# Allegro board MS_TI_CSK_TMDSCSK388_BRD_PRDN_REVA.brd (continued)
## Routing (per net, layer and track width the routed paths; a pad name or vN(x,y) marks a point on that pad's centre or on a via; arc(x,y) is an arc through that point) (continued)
N14434808: length 4.5
  TOP w0.102: v1(52.6,15.29) 52.55,15.34 52.08,15.34 52.08,15.34 U7.J19
  BOTTOM w0.102: v1(52.6,15.29) 53.03,15.29 53.11,15.22 55.19,15.22 55.66,14.75 C155.1
N14434812: length 4.2
  TOP w0.102: U7.W23 46.48,12.85 v1(46.45,12.83)
  BOTTOM w0.102: C180.1 45.88,10.07 45.87,10.07 45.87,11.54 45.89,11.55 45.89,12.26 v1(46.45,12.83)
N14445231: length 9.8
  TOP w0.102: U1.N1 38.29,47.68 v2(38.31,47.68)
  TOP w0.14: TP9.1 v1(45.5,47.37)
  L06_SIG2 w0.102: 39.55,47.68 v2(38.31,47.68)
  L06_SIG2 w0.119: 39.55,47.68 41.46,47.68 42.1,48.32 42.56,48.32 42.8,48.08 44.78,48.08 v1(45.5,47.37)
N14486422: length 1.7
  TOP w0.14: LD1.2 v1(47.14,50.22)
  BOTTOM w0.14: R88.2 47.1,50.18 v1(47.14,50.22)
N14519770: length 10.5
  TOP w0.102: U7.B6 55.27,21.54 55.71,21.54 56.06,21.9 56.77,21.9 57.31,22.43
  TOP w0.14: 57.31,22.43 57.61,22.74 57.61,24.91 57.96,25.26 57.96,26.32 57.55,26.73 57.55,27.77 58.44,28.67 R63.1
N14522090: length 2.3
  TOP w0.102: U7.AL6 39.51,21.84 38.94,22.4
  TOP w0.14: R73.2 38.62,22.4 38.94,22.4
N14522146: length 8
  TOP w0.102: v1(43.33,19.69) 43.14,19.88 43.14,20.66 42.98,20.82 U7.AF8
  BOTTOM w0.102: 38.94,21.57 39.07,21.44 41.76,21.44 41.79,21.41 42.25,21.41 43.33,20.33 v1(43.33,19.69)
  BOTTOM w0.14: R114.2 38.57,21.94 38.94,21.57
N14553661: length 6.6
  TOP w0.102: v1(45.49,20.85) 45.46,20.85 44.98,20.38 U7.AB9
  BOTTOM w0.102: R116.2 50.47,20.97 50.01,20.51 49.61,20.51 49.12,21 48.56,21 47.98,20.42 46.72,20.42 46.28,20.85 v1(45.49,20.85)
N14554807: length 6.3
  TOP w0.102: TP12.1 38.36,46.1 38,46.1 37,47.1 37,47.27 36.92,47.35 36.92,48.4 U1.L2
N14554839: length 11.7
  TOP w0.102: U1.G3 v1(34.55,49.38)
  TOP w0.14: v1(42.7,47.12) 42.7,47.26 43.06,47.63 TP10.1
  L06_SIG2 w0.102: 39.55,47.36 38.57,47.36 38.48,47.28 38.07,47.28 37.29,48.06 34.88,48.06 34.55,48.38 v1(34.55,49.38)
  L06_SIG2 w0.119: 39.55,47.36 42.05,47.36 42.12,47.3 42.12,47.3 42.3,47.12 v1(42.7,47.12)
N14559309: length 7.3
  TOP w0.102: U7.AJ4 41.48,23.34 41.44,23.38 v1(41.44,23.38)
  BOTTOM w0.102: 40.95,26.59 40.97,26.57 40.97,26.41 41.41,25.98 41.41,25.68 41.99,25.1 41.99,23.93 v1(41.44,23.38)
  BOTTOM w0.14: R104.1 39.51,28.74 39.98,28.27 40.11,28.27 40.57,27.81 40.57,26.98 40.95,26.59
N14559352: length 3
  TOP w0.102: v1(39.32,22.64) 40.66,22.64 40.95,22.34 U7.AK5
  BOTTOM w0.102: v1(39.32,22.64) 39.32,22.76 38.94,23.14
  BOTTOM w0.14: R110.1 38.77,23.31 38.94,23.14
N14559366: length 1.8
  TOP w0.102: v1(39.73,22.23) 39.84,22.34 U7.AL5
  BOTTOM w0.102: R111.1 39.76,22.19 v1(39.73,22.23)
N14559434: length 4.1
  TOP w0.102: U7.AK2 41.27,24.14 41.27,24.52 41.02,24.77 v1(41.02,24.84)
  BOTTOM w0.102: 38.94,24.51 39.51,24.51 39.66,24.36 40.54,24.36 v1(41.02,24.84)
  BOTTOM w0.14: 38.94,24.51 38.57,24.88 R109.1
N14564270: length 1.4
  TOP w0.14: U5.4 64.62,34.44 R52.2
N14564274: length 1.5
  TOP w0.14: R41.2 64.5,34.94 U5.5
N14564278: length 1.7
  TOP w0.14: R38.2 63.99,35.44 U5.6
N14564302: length 1.6
  TOP w0.14: R57.2 64.1,33.94 U5.3
N14564360: length 3.3
  TOP w0.14: R62.2 64.82,31.4 R58.1 64.19,32.21 63.49,32.91 U5.2
N14565290: length 1.5
  BOTTOM w0.14: R92.1 45.19,54.99 45.24,55.04 U12.3
N14565662: length 1.7
  BOTTOM w0.14: U12.2 45.74,54.91 R91.2
N14567220: length 5.7
  TOP w0.102: U7.AB30 45.02,9.84 45.27,9.58 45.27,8.48 45.23,8.44 45.23,7 45.62,6.6 45.62,5.59 45.5,5.46 45.5,5.45 v1(45.44,5.39)
  BOTTOM w0.14: R136.1 45.11,5.07 v1(45.44,5.39)
N14567296: length 5.4
  TOP w0.102: U7.W30 46.76,9.56 46.76,8.86 47.15,8.48 v1(47.15,7.62)
  BOTTOM w0.14: R135.2 48.63,5.82 48.13,6.33 48.13,7.36 47.87,7.62 v1(47.15,7.62)
N14568444: length 2.6
  TOP w0.102: v1(44.43,10.97) 44.29,10.84 U7.AD28
  BOTTOM w0.102: R127.1 43.46,9.79 43.97,10.29 43.97,10.52 v1(44.43,10.97)
N14568464: length 5.4
  TOP w0.102: v1(44.92,12.95) 44.54,13.34 U7.AC23
  BOTTOM w0.102: v1(44.92,12.95) 43.7,11.73 43.7,10.47 42.49,9.25 R128.2
N14568476: length 9.6
  TOP w0.102: U7.AF27 42.58,11.34 v1(42.51,11.42)
  BOTTOM w0.102: 41.86,7.79 41.86,9.48 42.29,9.91 42.55,9.91 43.19,10.55 43.19,11.16 42.94,11.42 v1(42.51,11.42)
  BOTTOM w0.14: 41.86,7.79 41.86,7.06 41.45,6.66 41.45,6.08 40.54,5.17 40.54,4.77 40.07,4.3 R139.1
N14572177: length 2.6
  TOP w0.14: MOD1.42 TP6.1
N14572181: length 5.1
  TOP w0.14: MOD1.43 50.84,54.49 50.76,54.41 49.2,54.41 TP5.1
N14575481: length 4.2
  TOP w0.61: 19.3,66.86 19.36,66.8
  TOP w0.635: 19.36,66.8 L3.1 C2.2 ; A1.1 19.3,66.86
N14575485: length 4.3
  TOP w0.61: 75.89,66.94 75.84,66.94 ; 76.79,64.85 76.78,64.86
  TOP w0.635: 76.78,64.86 76.78,66.05 arc(76.52,66.68) 75.89,66.94 ; 75.84,66.94 L2.1 C1.2 ; A2.1 76.79,64.85
N14575533: length 29.9
  TOP w0.635: R4.2 32.38,63.49 arc(30.8,63.81) 29.46,64.7 28.41,65.75 arc(27.25,66.53) 25.88,66.8 R1.2 C2.1
N14575591: length 9
  TOP w0.635: R5.2 66.19,63.49 arc(67.72,63.8) 69.02,64.66 70.3,65.94 arc(71.4,66.68) L1.1 C1.1
N14595953: length 2.9
  TOP w0.14: R71.2 62.49,25.04 R69.2 63.28,24.49 63.08,24.29 D1.3
N14599932: length 3.4
  TOP w0.102: U7.B19 57.16,15.34 57.31,15.19 57.31,14.99
  TOP w0.14: R78.1 57.46,14.83 57.31,14.99
N14599936: length 2.5
  TOP w0.102: 57.31,15.84 57.24,15.77 55.54,15.77 U7.A18
  TOP w0.14: R77.1 57.6,16.13 57.31,15.84
N14600104: length 1.5
  TOP w0.102: v1(49,10.36) 49.02,10.34 U7.N29
  BOTTOM w0.102: v1(49,10.36) 49.05,10.3 R124.1
N14600252: length 4.9
  TOP w0.102: U7.K31 50.83,9.19 50.83,7.98 50.91,7.91 50.91,4.99 C64.1
N14600256: length 4.9
  TOP w0.102: U7.L31 50.63,9.19 50.63,5.06 50.25,4.68 C63.1
N14600268: length 5.8
  TOP w0.102: U7.H31 52.14,9.34 52.2,9.28 52.2,9.18 52.07,9.04 51.96,9.04 51.88,8.97 51.88,8.74 52.55,8.07 52.55,7.98 52.62,7.91 52.62,7.79 52.76,7.65 52.76,6.91 52.89,6.79 52.89,5.26 52.99,5.16 53.24,5.16 53.37,5.03 C66.1
N14600316: length 5.8
  TOP w0.102: U7.H30 51.68,9.54 51.68,8.65 52.35,7.99 52.35,7.67 52.48,7.53 52.48,6.8 52.61,6.67 52.61,4.94 C65.1
N14600424: length 4.4
  TOP w0.102: R74.2 58.79,21.08 57.72,20 56.47,20 56.47,20 55.82,20 55.68,19.86 55.38,19.86 55.36,19.84 U7.B10
N14600444: length 4.3
  TOP w0.102: U7.B11 55.27,19.64 55.74,19.64 55.87,19.76 56.95,19.76 56.98,19.8 58.52,19.8 58.61,19.89 R76.2
N14634458: length 2.4
  TOP w0.14: SW1.1 37.49,34.02 38.43,33.08 R59.2
N14645029: length 13.4
  TOP w0.14: TP2.1 v1(42.19,60.48) ; U1.L6 36.45,51.47 35.88,51.47 35.88,51.47 v2(35.81,51.47)
  L06_SIG2 w0.102: v2(35.81,51.47) 36.13,51.79 36.13,51.79 38.74,54.4
  L06_SIG2 w0.119: v1(42.19,60.48) 39.09,57.38 39.09,54.76 38.74,54.4
N14648093: length 8
  TOP w0.102: U7.F30 52.98,9.01 53.6,8.39 53.69,8.39 54.28,7.79
  TOP w0.127: 54.53,7.09 C59.2
  TOP w0.14: Y2.1 57.98,6.59 57.27,7.3 56.07,7.3 55.86,7.09 C59.2 ; 54.28,7.79 54.28,7.34 54.53,7.09
N14719275: length 8.9
  TOP w0.102: U1.F4 32.78,49.46 v2(32.78,49.35)
  TOP w0.14: v1(29.49,43.69) 29.49,43.29 R19.1
  BOTTOM w0.102: v2(32.78,49.35) 32.78,46.98 32.11,46.3
  BOTTOM w0.14: 32.11,46.3 v1(29.49,43.69)
N14719324: length 3.2
  TOP w0.102: v1(39.48,24.97) 39.78,25.27 40.12,25.27 40.46,24.93 40.46,24.85 U7.AK1
  BOTTOM w0.102: v1(39.48,24.97) 39.17,25.27 39.17,25.68 39,25.85
  BOTTOM w0.14: 39,25.85 R106.1
N14776629: length 7
  TOP w0.102: v1(44.44,10.36) 44.42,10.34 U7.AD29
  BOTTOM w0.102: v1(44.44,10.36) 43.97,9.89 43.97,7.79
  BOTTOM w0.14: R138.2 42.61,4.68 43.97,6.04 43.97,7.79
N14776712: length 5.4
  TOP w0.102: U7.AD30 43.98,9.02 44.15,8.85 44.15,6.08 44.12,6.05 v1(44.12,5.61)
  BOTTOM w0.14: v1(44.12,5.61) 44.12,5.56 43.84,5.29 R137.1
N14776785: length 4.8
  TOP w0.102: U7.N24 49.01,12.84 v1(48.99,12.81)
  BOTTOM w0.102: R129.1 50.49,9.2 49.38,10.31 49.38,10.51 49.38,10.52 49.38,11.1 49.37,11.11 49.37,12.39 49.37,12.4 49.37,12.44 v1(48.99,12.81)
N14776789: length 3.1
  TOP w0.102: v1(50.48,10.33) 50.47,10.34 U7.M29
  BOTTOM w0.102: v1(50.48,10.33) 50.78,10.02 50.79,10.02 50.83,9.98 52.12,9.98 52.65,9.46 R123.1
N14783196: length 10.5
  TOP w0.102: U7.W31 46.48,8.86 46.57,8.77 46.57,8.76 46.77,8.57 46.77,7.78 46.77,7.78 46.77,7.46 46.77,7.46 46.77,7.4 46.97,7.2 v1(47.73,7.2)
  L03_SIG1 w0.119: v1(47.73,7.2) 47.28,6.75 47.28,6.31 48.72,4.88 51.17,4.88 51.75,5.46 v1(52.1,5.46)
  BOTTOM w0.14: v1(52.1,5.46) 52.24,5.6 RA13.4
N14783200: length 11.7
  TOP w0.102: v1(47.7,6.48) 47.39,6.18 46.23,6.18 45.9,6.51 45.9,6.71 45.52,7.09 45.52,7.79 45.48,7.83 45.48,8.4 U7.AA30
  L03_SIG1 w0.119: v1(51.34,5.63) 50.85,5.15 49.04,5.15 v1(47.7,6.48)
  BOTTOM w0.14: v1(51.34,5.63) 51.64,5.33 51.64,5.32 51.98,4.98 52.28,4.98 52.4,5.1 RA13.3
N14783204: length 9.7
  TOP w0.102: U7.U29 47.04,10.34 v1(47.02,10.36)
  L06_SIG2 w0.102: 48.2,7.79 47.93,8.06 47.93,8.06 47.02,8.97 v1(47.02,10.36)
  L06_SIG2 w0.119: v1(50.15,6.74) 49.25,6.74 48.2,7.79
  BOTTOM w0.14: RA13.2 51.71,4.6 50.83,5.49 50.83,6.05 v1(50.15,6.74)
N14783208: length 12.3
  TOP w0.102: v1(46.47,11.63) 46.18,11.34 U7.Y27
  L06_SIG2 w0.102: 47.82,7.79 45.88,9.73 45.88,11.03 v1(46.47,11.63)
  L06_SIG2 w0.119: 47.82,7.79 49.5,6.1 v1(50.14,6.1)
  BOTTOM w0.14: RA13.1 51.5,4.1 50.14,5.46 v1(50.14,6.1)
N15013442: length 2.3
  TOP w0.635: R2.2 J1.1
N15014410: length 2.3
  TOP w0.635: J2.1 R3.2
N15102842: length 10.1
  TOP w0.102: v1(57.06,11.6) 57.02,11.56 57.31,11.56 ; U7.M21 v1(49.58,14.34)
  TOP w0.14: R79.2 57.31,11.56
  BOTTOM w0.102: v1(57.06,11.6) 56.21,12.45 54.77,12.45 54.16,13.06 52.14,13.06 51.92,12.83 51.06,12.83 50.89,13 50.89,13.03 50.89,13.04 50.89,13.54 50.56,13.87 50.06,13.87 v1(49.58,14.34)
N15102865: length 4
  TOP w0.102: U7.E30 53.18,9.54 53.18,9.24 53.78,8.64 53.84,8.64 v1(54.68,7.79)
  BOTTOM w0.14: v1(54.68,7.79) 55.49,6.99 R134.2
N15102869: length 5.4
  TOP w0.102: v1(53.97,11.12) 53.69,10.84 U7.E28 ; 57.31,9.65 57.18,9.78 v1(56.87,9.78)
  TOP w0.14: 57.31,9.65 R80.2
  BOTTOM w0.102: v1(56.87,9.78) 56.87,10.67 56.42,11.12 v1(53.97,11.12)
N15102988: length 4.6
  TOP w0.102: U7.AG2 42.48,23.86 42.76,24.14 42.76,25.8 42.27,26.29 42.27,26.59
  TOP w0.14: R65.2 41.39,26.98 41.88,26.98 42.27,26.59
N15110091: length 1.5
  TOP w0.14: R54.1 59.39,34.44 U5.13
N15110100: length 1.3
  TOP w0.14: U5.12 58.88,34.94 R47.1
N15110106: length 1.4
  TOP w0.14: U5.11 59.26,35.44 R39.1
N15110404: length 7.1
  BOTTOM w0.14: U12.11 43.74,60.5 44.42,61.18 46.72,61.18 47.17,60.73 47.17,59.87 47.3,59.74 R87.1
N15110444: length 1.8
  BOTTOM w0.14: U12.6 43.74,55.16 43.04,54.47 R90.2
N15123588: length 2.3
  TOP w0.102: U7.Y29 46.43,10.34 v1(46.46,10.36)
  BOTTOM w0.102: v1(46.46,10.36) 46.91,9.91 47.34,9.91 47.87,9.38 R125.2
N15123674: length 1.8
  TOP w0.102: v1(45,10.36) 45.02,10.34 U7.AA29
  BOTTOM w0.102: v1(45,10.36) 44.48,9.84 R126.1
N15123798: length 6.7
  TOP w0.102: v1(44.98,10.96) 45.1,10.84 U7.AA28
  BOTTOM w0.102: v1(44.98,10.96) 45.38,10.56 45.38,10.17 45.08,9.87 45.08,7.79
  BOTTOM w0.14: RA12.5 45.08,6.67 45.08,7.79
N15123807: length 7.6
  TOP w0.102: U7.AA26 45.19,11.84 v1(44.99,11.63)
  BOTTOM w0.102: v1(44.99,11.63) 45.58,11.04 45.58,10.09 45.37,9.88 45.37,7.79
  BOTTOM w0.14: 45.37,7.79 45.37,7.04 46.26,6.16 46.41,6.16 46.69,5.88 RA12.6
N15123817: length 4.5
  TOP w0.102: U7.Y31 45.98,8.96 46.51,8.42 46.51,7.14 46.39,7.02 v1(46.39,6.59)
  BOTTOM w0.14: v1(46.39,6.59) 46.71,6.27 46.89,6.27 47.19,5.97 RA12.7
N15123828: length 5.7
  TOP w0.102: U7.Y30 45.98,9.84 45.68,9.54 45.68,8.87 46.26,8.3 46.26,7.81 46.15,7.71 46.15,7.32
  TOP w0.14: 46.15,7.32 v1(46.03,7.2)
  BOTTOM w0.14: v1(46.03,7.2) 46.48,7.2 47.27,6.41 47.27,6.31 47.69,5.89 RA12.8
N15124532: length 6.1
  TOP w0.102: U7.AG6 42.48,22.23 42.43,22.27 v1(42.43,22.33)
  BOTTOM w0.102: v1(42.43,22.33) 42.43,22.76 42.4,22.79 42.4,26.57 42.38,26.59
  BOTTOM w0.14: 42.38,26.59 42.29,26.68 R105.1
N15124704: length 1.7
  TOP w0.14: MOD1.6 v1(65.89,53.79)
  BOTTOM w0.14: R93.2 65.88,53.79 v1(65.89,53.79)
N15124708: length 1.7
  TOP w0.14: MOD1.8 v1(65.89,55.19)
  BOTTOM w0.14: v1(65.89,55.19) 65.85,55.16 R89.2
N15124784: length 1.8
  TOP w0.14: MOD1.10 v1(65.89,56.59)
  BOTTOM w0.14: RA5.4 65.66,56.82 v1(65.89,56.59)
N15124788: length 3
  TOP w0.14: MOD1.11 v1(66.55,57.29)
  BOTTOM w0.14: v1(66.55,57.29) 66.1,57.29 66.07,57.32 RA5.3
N15124799: length 3.2
  TOP w0.14: MOD1.13 v1(66.55,58.69)
  BOTTOM w0.14: v1(66.55,58.69) 65.98,58.69 65.61,58.32 RA5.1
N15124807: length 1.8
  TOP w0.14: MOD1.12 v1(65.89,57.99)
  BOTTOM w0.14: v1(65.89,57.99) 65.72,57.82 RA5.2
N15124875: length 2.7
  TOP w0.14: MOD1.60 61.15,49 61.14,48.99 61.14,47.85 61.61,47.38 R13.2
N15140205: length 8.4
  TOP w0.14: U6.L8 25.91,16.95 25.91,15.73 25.16,14.97 R119.2
N15266407: length 1.9
  TOP w0.102: U7.AC8 44.85,20.84 44.92,20.91 v1(44.93,20.91)
  BOTTOM w0.102: v1(44.93,20.91) 44.6,20.91 44.28,21.23 R115.1
N15454827: length 1.7
  TOP w0.102: v1(47.01,12.41) 47.01,12.41 47.48,11.94 U7.U26
  BOTTOM w0.102: R133.1 47.14,12.41 v1(47.01,12.41)

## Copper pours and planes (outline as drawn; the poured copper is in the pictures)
DGND on TOP: 68.66,46.07 68.66,59.64 68.41,59.89 64.57,59.89 63.81,60.66 54.06,60.66 53.32,59.92 52,59.92 50.36,61.56 7.78,61.56 7.78,68.81 8.74,68.81 8.74,69.49 11.36,69.49 11.36,69.33 14.63,69.33 14.63,69.27 20.96,69.27 20.96,69.49 78.03,69.49 78.77,68.76 78.77,46.07 ; 2 cut-outs
DGND on TOP: 20.6,50.67 22.13,50.67 22.64,51.18 22.89,51.18 23.02,51.05 23.02,50.29 22.89,50.17 20.73,50.17 20.6,50.29
DGND on TOP: 37.11,52.45 38.38,52.45 38.76,52.83 38.76,53.21 38.64,53.34 37.88,53.34 37.37,52.83 37.24,52.83 37.11,52.71
DGND on TOP: 8.39,0.76 7.78,1.37 7.78,60.96 12.98,60.96 13.11,61.09 35.46,61.09 35.59,60.96 50.14,60.96 51.52,59.59 53.8,59.59 54.11,59.89 63.91,59.89 64.65,59.16 67.59,59.16 67.59,45.47 79.02,45.47 79.02,1.7 78.08,0.76 ; 22 cut-outs
DGND on TOP: 35.08,53.98 35.08,51.94 35.21,51.82 35.34,51.82 35.46,51.94 35.46,53.09 36.35,53.98 36.35,54.99 36.22,55.12 35.84,55.12 35.84,54.74
DGND on TOP: 13.87,22.73 14.63,21.97 14.63,20.19 15.78,20.19 15.9,20.32 15.9,24.77 15.65,25.02 14,25.02 13.87,24.89
DGND on TOP: 41.81,56.13 42.07,56.39 42.07,58.17 41.81,58.42 38.89,58.42 38.76,58.29 38.76,56.26 38.89,56.13
DGND on TOP: 23.78,48.01 23.78,47.12 23.91,46.99 25.56,46.99 25.68,47.12 25.68,48.01 25.56,48.13 23.91,48.13
DGND on TOP: 35.21,50.17 35.72,50.17 35.97,49.91 35.97,49.53 36.1,49.4 36.1,49.28 35.97,49.15 35.72,49.15 35.59,49.02 35.59,46.99 36.1,46.48 37.11,46.48 37.75,45.85 38.13,45.85 39.15,44.83 39.15,43.18 39.02,43.05 38.26,43.05 38.13,43.18 38.13,44.58 37.62,45.09 36.73,45.09 35.08,46.74 35.08,50.04
DGND on BOTTOM: 43.88,32.07 43.88,30.82 44.02,30.68 49.7,30.68 50.11,30.26 50.11,28.26 50.51,27.86 51.77,27.86 52.09,28.18 52.09,31.57 51.89,31.77 49.25,31.77 48.85,32.16 48.85,33.21 48.55,33.51 47.04,33.51 46.63,33.1 46.63,32.61 46.18,32.16 44.04,32.16 44.01,32.19
DGND on BOTTOM: 8.47,0.64 7.51,1.6 7.51,68.33 7.99,68.81 8.79,68.81 8.87,68.73 10.01,68.73 10.54,69.27 10.54,69.22 20.96,69.22 20.96,69.49 78.01,69.49 79.04,68.46 79.04,1.8 77.88,0.64 49.2,0.64 48.24,1.6 41.94,1.6 40.97,0.64 ; 32 cut-outs
DGND on L02_GND1: 79.04,45.72 79.04,1.86 77.82,0.64 49.2,0.64 48.24,1.6 41.94,1.6 40.97,0.64 8.47,0.64 7.51,1.6 7.51,61.47 50.22,61.47 51.9,59.79 53.37,59.79 53.9,60.33 63.88,60.33 64.49,59.72 67.03,59.72 67.59,59.16 67.59,45.85 67.72,45.72 ; 4 cut-outs
DGND on L04_PWR1, L05_PWR2: 68.66,46.48 68.66,59.64 68.41,59.89 64.57,59.89 64.01,60.45 53.85,60.45 53.32,59.92 52,59.92 50.32,61.6 38.13,61.6 37.11,60.58 7.42,60.58 7.42,68.23 8,68.81 9.15,68.81 9.67,69.33 20.95,69.33 20.95,69.49 77.83,69.49 79.12,68.2 79.12,46.48
DGND on L07_GND2: 8.47,0.64 7.51,1.6 7.51,68.33 7.99,68.81 8.79,68.81 8.87,68.73 10.01,68.73 10.61,69.33 20.95,69.33 20.95,69.49 78.01,69.49 79.04,68.46 79.04,1.8 77.88,0.64 49.2,0.64 48.24,1.6 41.94,1.6 40.97,0.64 ; 5 cut-outs
VCC_3V3 on TOP: 11.84,21.21 11.84,18.8 11.97,18.67 15.02,18.67 15.14,18.8 15.14,19.81 15.02,19.94 14.51,19.94 14.51,20.7 14.13,21.08 14.13,22.23 12.98,22.23 12.98,21.34 12.86,21.21
VCC_3V3 on BOTTOM: 35.34,40.77 35.34,36.45 35.59,36.2 36.48,36.2 36.48,40.64 36.22,40.89 35.46,40.89
VCC_3V3 on L04_PWR1: 49.89,60.55 51.57,58.88 53.98,58.88 54.51,59.41 63.3,59.41 63.94,58.78 65.92,58.78 67.34,57.35 67.34,45.54 67.42,45.47 78.9,45.47 78.92,45.44 78.92,1.45 78.16,0.69 49.25,0.69 48.29,1.65 45.19,1.65 44.23,0.69 8.36,0.69 7.8,1.25 7.8,59.49 37.57,59.49 38.64,60.55 ; 9 cut-outs
VCC_3V3 on L05_PWR2: 7.8,22.61 13.49,22.61 14,23.11 14,27.43 17.3,30.73 21.21,30.73 25.05,34.57 25.05,35.43 25.18,35.56 33.3,35.56 35.72,37.97 39.4,37.97 45.11,43.69 45.11,46.1 55.86,46.1 56.54,45.42 56.54,26.92 49.56,19.94 49.05,19.94 48.54,20.45 46.64,20.45 46.38,20.7 39.78,20.7 37.75,22.73 37.75,29.72 36.99,30.48 28.03,30.48 27.13,29.58 27.13,28.04 27.63,27.55 28.36,27.55 28.59,27.31 28.59,25.94 28.31,25.65 22,25.65 20.35,24 20.35,4.06 21.62,2.79 38.76,2.79 45.62,9.65 45.62,11.94 45.75,12.07 45.75,13.34 45.24,13.84 45.24,15.88 45.62,16.26 45.62,20.07 45.75,20.19 46.89,20.19 47.02,20.07 47.02,13.34 48.67,11.68 62.39,11.68 69.12,18.42 69.12,43.05 67.99,44.18 67.99,45.56 68.1,45.67 78.92,45.67 78.92,1.68 77.93,0.69 49.18,0.69 48.24,1.63 45.19,1.63 44.25,0.69 8.36,0.69 7.8,1.25 ; 7 cut-outs
VCC_5V0 on TOP: 11.76,60.05 10.75,60.05 10.74,60.03 8.63,60.03 8.41,59.82 8.41,48.9 8.69,48.62 10.65,48.62 10.7,48.57 15.07,48.57 15.12,48.62 15.12,49.91 11.89,49.91 11.76,50.04
VCC_5V0 on TOP: 39.78,50.04 39.78,49.91 39.53,49.66 37.75,49.66 37.75,49.15 38,49.15 38.13,49.28 39.53,49.28 39.78,49.02 39.78,48.64 39.91,48.51 41.3,48.51 41.43,48.64 41.43,49.91 41.05,50.29 40.03,50.29
VCC_5V0 on TOP: 23.14,34.67 24.01,34.67 24.29,34.95 24.29,38 24.54,38.25 24.54,40.77 22,40.77 21.75,41.02 21.75,41.4 21.49,41.66 18.19,41.66 18.06,41.53 18.06,39.24 22.64,39.24 23.14,38.74
VCC_5V0 on TOP: 30.38,50.55 31.02,51.18 31.02,51.44 30.89,51.56 30.64,51.56 30.26,51.18 29.24,51.18 28.35,52.07 23.78,52.07 23.65,51.94 23.65,50.67 23.78,50.55
VCC_5V0 on BOTTOM: 16.29,41.15 16.29,39.24 16.41,39.12 22.25,39.12 22.28,39.14 23.12,39.14 23.22,39.24 23.22,39.8 21.49,41.53 16.67,41.53
VCC_5V0 on L05_PWR2: 46.83,53.66 46.83,48.07 44.86,46.1 44.86,43.94 39.15,38.23 35.72,38.23 33.18,35.69 24.86,35.69 24.86,34.91 20.87,30.93 17.11,30.93 13.62,27.43 13.62,26.29 12.98,25.65 12.98,23.11 12.67,22.8 8.54,22.8 7.8,23.54 7.8,59.82 8,60.02 36.66,60.02 37.25,59.42 37.25,57.04 37.82,56.47 44.02,56.47 ; 4 cut-outs
VDD_DDR on TOP: 33.43,28.83 33.81,28.45 38,28.45 38.38,28.83 38.38,30.61 37.11,30.61 36.61,31.12 36.61,33.4 35.46,34.54 35.46,38.99 35.21,39.24 33.15,39.24 33.1,39.19 33.1,34.06 33.43,33.73
VDD_DDR on L04_PWR1: 19.92,5.02 16.6,8.33 16.6,12.24 17.1,11.75 19.79,11.75 20.03,11.99 20.03,16.43 20.1,16.5 20.1,23.5 22.06,25.46 22.06,28.77 25.19,28.77 25.43,29.01 25.43,32 25.87,32.45 34.11,32.45 41.11,25.45 41.11,22.11 40.16,21.15 40.16,14.48 40.03,14.35 40.03,8.4 36.65,5.02
VDD_DDR on L05_PWR2: 39.53,20.45 45.18,20.45 45.43,20.19 45.43,16.64 44.86,16.07 44.86,13.78 45.43,13.21 45.43,9.78 38.7,3.05 21.75,3.05 20.67,4.13 20.67,23.75 22.19,25.27 28.57,25.27 28.97,25.67 28.97,27.6 28.64,27.94 27.73,27.94 27.46,28.2 27.46,29.44 28.25,30.23 36.86,30.23 37.49,29.59 37.49,22.48 ; 1 cut-out
VDDR_VTT on TOP: 17.07,14.96 19.18,14.96 19.43,15.22 19.43,20.07 19.18,20.32 17.07,20.32 16.82,20.07 16.82,15.22
VDDR_VTT on BOTTOM: 23.91,30.61 24.62,30.61 24.79,30.43 24.79,30.02 25.1,29.72 25.35,29.72 25.63,30 25.89,30 25.96,29.92 25.96,29.08 25.76,28.88 24.08,28.88 23.7,29.26 23.7,30.4
VDDR_VTT on BOTTOM: 18.27,16 17.68,15.42 17.68,12.45 17.81,12.32 18.27,12.32 18.29,12.29 18.88,12.29 18.93,12.35 18.93,15.77 18.9,15.8 18.9,16.08 19.16,16.33 19.16,17.98 19.71,18.54 22.38,18.54 22.51,18.42 23.78,18.42 23.91,18.29 23.91,17.4 24.54,17.4 24.67,17.53 24.67,18.92 24.92,19.18 24.92,21.21 23.78,21.21 23.27,20.7 22.18,20.7 22.18,21.41 22,21.59 21.21,21.59 20.88,21.92 20.88,24.67 21.14,24.92 23.52,24.92 23.55,24.89 27.08,24.89 27.08,25.91 26.83,26.16 26.83,27.2 26.78,27.26 25.02,27.26 25.02,26.09 24.92,25.99 23,25.99 22.93,26.06 22.93,27.13 22.24,27.13 21.68,27.69 21.24,27.69 21.11,27.56 21.11,25.78 19.69,25.78 19.56,25.65 19.56,22.73 19.33,22.51 19.33,19.43 19.21,19.3 18.27,19.3
VDDR_VTT on L04_PWR1: 17.25,12.13 16.6,12.78 16.6,33.53 17.68,33.53 18.76,32.45 19.75,32.45 19.76,32.45 24.49,32.45 24.9,32.04 24.9,29.46 24.58,29.15 21.68,29.15 21.68,25.7 19.65,23.67 19.65,12.14 19.64,12.13
(no net) on TOP: 31.96,41.02 31.96,45.21 32.51,45.76 32.51,48.13 33.18,48.8 33.18,49.4 33.3,49.53 33.43,49.53 33.56,49.4 33.56,48.77 32.92,48.13 32.92,46.29 32.98,46.23 33.68,46.23 33.81,46.36 33.81,48.85 34.19,48.85 34.19,45.97 34.7,45.47 34.7,44.58 35.21,44.07 35.21,42.8 33.3,42.8 33.3,41.02
(no net) on L03_SIG1: 8.47,0.64 7.51,1.6 7.51,61.47 50.22,61.47 51.9,59.79 53.37,59.79 53.9,60.33 63.88,60.33 64.49,59.72 67.14,59.72 67.59,59.26 67.59,45.85 67.72,45.72 79.04,45.72 79.04,1.86 77.82,0.64 49.2,0.64 48.24,1.6 41.94,1.6 40.97,0.64 ; 106 cut-outs
(no net) on L06_SIG2: 79.04,45.72 79.04,1.86 77.82,0.64 49.2,0.64 48.24,1.6 41.94,1.6 40.97,0.64 8.47,0.64 7.51,1.6 7.51,61.47 50.22,61.47 51.9,59.79 53.37,59.79 53.9,60.33 63.88,60.33 64.49,59.72 67.03,59.72 67.59,59.16 67.59,45.85 67.72,45.72 ; 78 cut-outs
BB_PMIC_3V3 on TOP: 9.94,42.55 9.94,40.64 11.21,39.37 13.24,39.37 13.49,39.62 13.49,41.78 12.73,42.55
BB_PMIC_3V3 on BOTTOM: 12.48,38.1 12.6,38.23 12.6,42.16 12.48,42.29 10.32,42.29 10.25,42.23 8.73,42.23 8.16,41.66 8.16,36.7 8.28,36.58 10.7,36.58 10.82,36.7 11.71,36.7 11.71,36.96 10.82,36.96 10.57,37.21 9.94,37.21 9.81,37.34 9.81,37.85 10.06,38.1
BB_VCC3V3 on TOP: 11.33,20.57 11.46,20.7 11.46,21.34 11.59,21.46 12.6,21.46 12.73,21.59 12.73,22.23 12.6,22.35 8.28,22.35 8.16,22.23 8.16,20.7 8.28,20.57
BB_VCC3V3 on BOTTOM: 12.73,20.57 12.86,20.7 12.86,21.97 12.73,22.1 10.7,22.1 10.57,21.97 8.41,21.97 8.28,21.84 8.28,20.7 8.41,20.57
CORE_CVDD on TOP: 16.92,44.07 16.92,42.67 17.3,42.29 21.49,42.29 21.75,42.55 21.75,43.94 21.62,44.07
CORE_CVDD on BOTTOM: 44.12,30.28 44.12,29.31 44.25,29.18 45.33,29.18 45.7,29.56 48.09,29.56 48.15,29.62 48.15,30.25 48.05,30.35 44.2,30.35
CORE_CVDD on L04_PWR1: 41.49,21.95 41.49,25.61 34.27,32.83 18.63,32.83 17.11,34.35 17.11,42.85 18.65,44.39 21.87,44.39 22.32,43.94 22.32,39.04 24.33,37.02 36.78,37.02 39.7,34.1 46.81,34.1 47.53,33.39 47.53,31.37 48.8,30.1 48.8,27.69 47.98,26.87 47.98,21.69 47.55,21.25 47.55,15.13 46.26,13.84 45.24,13.84 45.11,13.72 45.11,13.46 44.86,13.21 40.54,13.21 40.42,13.34 40.42,20.87
CORE_CVDD on L05_PWR2: 46.26,19.16 46.96,19.16 47.78,18.34 50.12,18.34 50.73,17.73 50.73,16.13 50.64,16.05 48.63,16.05 47.66,15.08 45.97,15.08 45.48,15.57 45.48,16.14 45.67,16.33 45.67,19.01 45.85,19.18 46.24,19.18
CVDD_ARM on TOP: 24.03,42.67 24.03,41.02 22.13,41.02 22.13,42.67
CVDD_ARM on L04_PWR1: 49.75,19.24 52.23,21.72 52.23,35.05 50.58,36.7 39.02,36.7 35.08,40.64 24.03,40.64 23.52,41.15 23.52,42.55 24.67,43.69 35.07,43.69 39,39.75 39.02,39.75 39.27,39.5 50.6,39.5 51.21,40.11 53.9,40.11 57.18,36.83 57.18,26.29 56.8,25.91 56.8,24.77 54.64,22.61 54.64,19.05 54.39,18.8 52.35,18.8 51.68,18.12 51.68,15.46 50.96,14.73 49.56,14.73 49.46,14.83 49.46,18.31 49.75,18.61
CVDD_HDVICP on TOP: 40.14,41.23 40.14,40.51 40.01,40.39 40.01,40.01 40.16,39.85 41.18,39.85 41.48,40.16 41.48,40.87 41.71,41.1 41.71,41.66 41.3,41.66 40.87,41.23
CVDD_HDVICP on L04_PWR1: 48.16,13.84 48.16,13.72 46.51,12.07 45.37,12.07 45.37,13.64 45.44,13.72 46.26,13.72 47.65,15.11 47.65,21.21 48.16,21.72 48.16,26.67 49.69,28.19 49.69,30.1 48.16,31.62 48.16,33.53 47.53,34.16 38.76,34.16 35.59,37.34 24.29,37.34 22.51,39.12 22.51,44.07 23.52,45.09 36.48,45.09 41.05,40.51 41.05,40.13 40.8,39.88 39.4,39.88 35.21,44.07 24.54,44.07 23.27,42.8 23.27,40.77 23.91,40.13 34.95,40.13 38.76,36.32 50.58,36.32 51.85,35.05 51.85,21.72 49.2,19.08 49.2,14.89
PMIC_3V3 on TOP (solid shape): 33.94,48.85 33.98,48.83 33.99,48.79 34,48.73 34,45.83 34.45,45.38 34.45,44.49 35.08,43.86 35.08,43.08 35.01,43.01 35.01,42.8 33.3,42.8 33.3,42.26 33.15,41.87 33.3,41.48 33.3,41.02 31.96,41.02 31.96,45.21 32.51,45.76 32.51,47.19 32.52,47.26 32.53,47.33 32.53,48.16 32.62,48.24 32.7,48.24 32.75,48.25 32.8,48.25 32.89,48.23 32.92,48.14 32.91,48.07 32.92,47.99 32.92,47.47 32.74,47.3 32.74,46.74 32.79,46.54 32.92,46.39 32.92,46.29 32.98,46.23 33.68,46.23 33.81,46.36 33.81,48.85
PMIC_3V3 on TOP: 40.16,53.59 40.54,53.98 41.3,53.98 41.3,55.63 41.18,55.75 37.88,55.75 37.75,55.63 37.75,54.1 36.35,52.71 36.35,51.94 36.48,51.82 36.86,51.82 36.86,52.71 37.75,53.59
PMIC_3V3 on TOP: 11.84,36.96 16.41,36.96 16.79,37.34 16.79,38.48 16.29,38.99 15.4,38.99 15.14,39.24 13.49,39.24 13.24,38.99 10.57,38.99 10.32,39.24 9.05,39.24 8.79,38.99 8.79,36.7 9.05,36.45 11.33,36.45
PMIC_3V3 on L05_PWR2: 38.67,51.08 38.67,50.32 34.57,46.23 34.57,41.72 34.19,41.34 33.68,41.34 33.3,40.96 28.61,40.96 27.62,41.94 19.49,41.94 16.41,38.86 16.41,37.34 15.78,36.7 12.73,36.7 12.48,36.96 12.48,38.23 13.05,38.8 13.05,42.29 14.89,44.13 14.89,48.77 15.27,49.15 21.87,49.15 22.57,49.85 26.32,49.85 29.82,53.34 32.99,53.34 33.87,54.23 33.87,56 34.35,56.48 42.35,56.48 43.02,55.82 43.02,54.62 42.19,53.79 38.63,53.79 38.07,53.22 38.07,51.69
REFGND on L02_GND1: 31.58,55.6 31.58,58.57 31.8,58.8 33.53,58.8 33.94,59.21 33.94,59.84 33.99,59.89 35.69,59.89 35.92,59.67 35.92,55.78 35.49,55.35 34.47,55.35 34.12,54.99 34.12,53.54 34.32,53.34 34.32,53.09 34.19,52.96 34.19,52.58 34.46,52.31 34.46,52.06 34.24,51.84 33.18,51.84 33.13,51.89 33.13,55.17 32.97,55.32 31.91,55.32 31.88,55.3
TPS_CORE_CVDD on TOP: 16.79,46.61 16.79,44.96 17.05,44.7 21.75,44.7 22.13,45.09 22.13,46.61 22,46.74 16.92,46.74
TPS_CORE_CVDD on TOP: 19.84,50.55 19.97,50.67 19.97,58.67 19.33,59.31 15.65,59.31 15.27,58.93 15.27,50.65 15.37,50.55
TPS_CORE_CVDD on L03_SIG1: 20.03,49.02 21.94,47.11 21.94,44.64 21.87,44.58 16.03,44.58 15.9,44.7 15.9,53.32 15.47,53.75 15.47,59.23 15.75,59.51 19.82,59.51 20.03,59.3
TPS_CVDD_ARM on TOP: 25.43,46.86 25.43,42.42 27.97,42.42 28.1,42.29 28.1,41.15 24.41,41.15 24.41,43.05 22.25,43.05 22.25,44.83 22.38,44.96 22.38,46.23 23.02,46.86
TPS_CVDD_HDVICP on TOP: 37.77,40.01 39.88,40.01 39.88,42.65 39.58,42.95 39.43,42.95 39.15,42.67 39.15,42.55 37.8,42.55 37.44,42.9 35.44,42.9 35.39,42.85 35.39,41.62 35.58,41.42 37.04,41.42 37.07,41.39 37.07,40.46 37.18,40.35 37.77,40.35
TPS_VDAC_1V8 on TOP: 39.65,53.09 39.65,52.32 39.4,52.07 39.02,52.07 38.51,51.56 37.75,51.56 37.75,51.18 39.15,51.18 39.27,51.31 40.42,51.31 40.54,51.44 40.54,53.09 40.42,53.21 39.78,53.21
TPS_VDDA_1V8 on TOP: 34.57,55.12 34.57,52.83 34.45,52.71 34.45,52.58 34.57,52.45 34.83,52.45 34.95,52.58 34.95,54.1 35.59,54.74 35.59,55.25 34.7,55.25
TPS_VDDA_1V8 on TOP: 36.1,60.83 36.1,58.8 36.22,58.67 38.51,58.67 38.64,58.8 41.18,58.8 41.3,58.93 41.3,60.71 41.18,60.83
TPS_VDDA_1V8 on L03_SIG1: 52.68,47.78 59.11,47.78 59.47,47.42 60.43,47.42 60.79,47.78 63.4,47.78 63.66,47.52 63.66,47.17 62.01,45.52 57.18,45.52 54.64,42.98 53.17,42.98 52.4,43.74 52.4,47.5
TPS_VDDA_1V8 on L05_PWR2: 48.67,11.94 48.04,12.57 48.04,14.1 47.82,14.31 47.82,14.95 48.82,15.95 50.17,15.95 50.27,15.85 51.9,15.85 52.28,16.23 52.28,18.24 51.87,18.64 47.27,18.64 47.27,20.19 48.54,20.19 48.92,19.81 49.69,19.81 56.8,26.92 56.8,34.8 57.94,35.94 57.94,46 57.59,46.36 48.29,46.36 47.15,47.5 47.15,54.08 43.97,57.25 38.26,57.25 38.26,60.73 38.61,61.09 50.04,61.09 51.79,59.34 53.65,59.34 54.11,59.79 63.1,59.79 63.99,58.9 65.92,58.9 66.3,59.28 66.86,59.28 67.59,58.55 67.59,44.07 68.86,42.8 68.86,18.54 62.26,11.94 ; 7 cut-outs
TPS_VDDA_1V8 on L06_SIG2: 59.26,32.51 64.62,32.51 65.49,33.38 65.49,36.58 66.91,38 66.91,41.33 66.07,42.16 61.29,42.16 60.96,42.5 60.96,44.35 63.02,46.41 63.63,46.41 64.34,47.12 64.34,56.62 63,57.96 50.85,57.96 50.27,57.38 50.27,47.63 51.03,46.86 53.78,46.86 56.87,49.96 59.39,49.96 60.13,49.23 60.13,48.03 57.94,45.85 57.94,40.67 59.21,39.4 59.21,37.44 59.19,37.42 59.19,32.59
N11847334 on TOP: 32.29,46.1 31.14,44.96 29.87,44.96 28.22,43.31 25.81,43.31 25.81,44.32 26.83,44.32 28.22,45.72 30.64,45.72 31.78,46.86 31.78,48.64 32.03,48.9 32.77,48.9 32.85,48.82 32.85,48.69 32.73,48.58 32.54,48.58 32.29,48.32
N11848351 on TOP: 34.45,48.9 34.83,48.9 34.83,46.74 36.73,44.83 37.58,44.83 37.75,44.66 37.75,44.66 37.83,44.58 37.83,43.54 37.79,43.5 36.76,43.5 36.73,43.47 36.73,43.5 35.59,43.5 35.59,44.07 34.95,44.7 34.95,45.59 34.45,46.1
N11848810 on TOP: 36.35,57.4 36.35,55.5 36.73,55.12 36.73,54.36 36.61,54.23 36.61,53.98 35.72,53.09 35.72,51.94 35.84,51.82 36.05,51.82 36.15,51.92 36.15,52.88 37.49,54.23 37.49,55.63 38.38,56.52 38.38,57.4
N12973023 on TOP: 25.68,48.39 26.06,48.01 26.83,48.01 28.48,49.66 28.99,49.66 29.11,49.78 30.26,49.78 30.26,50.17 27.72,50.17 27.33,49.78 16.16,49.78 15.65,49.28 15.65,48.39 15.52,48.26 13.49,48.26 13.36,48.13 13.36,46.48 13.62,46.23 15.27,46.23 16.03,46.99 22.64,46.99 24.03,48.39
N14067125 on TOP: 24.92,37.72 24.67,37.47 24.67,35.94 24.92,35.69 26.57,35.69 27.21,36.32 29.49,36.32 29.87,35.94 29.87,33.66 31.91,33.66 32.31,34.06 32.31,39.12 27.72,39.12 26.32,37.72
N14067125 on BOTTOM: 25.94,34.67 25.68,34.67 25.56,34.8 25.56,36.07 25.81,36.32 27.46,36.32 27.59,36.2 27.59,35.69 26.7,35.69 26.06,35.05 26.06,34.8

Small or netless copper shapes (teardrops, artwork), in the pictures only: 731 on TOP, 586 on BOTTOM, 316 on L03_SIG1, 3 on L04_PWR1, 11 on L05_PWR2, 323 on L06_SIG2

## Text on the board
Ref Des/Assembly Bottom: D | TMDSCSK388_PRDN_REVA BOTTOM ASSEMBLY.
Ref Des/Silkscreen Bottom: C | B | For evaluation only; not FCC approved for resale | ASSY REV:
User.Comments: CR_UNNAMED_1
Ref Des/Assembly Top: A8 | A1 | N8 | N1 | TMDSCSK388_PRDN_REVA TOP ASSEMBLY
Ref Des/Silkscreen Top: 5V0 | 3V3 | CORE | ARM | VDDA_1V8 | A | 1V1 | PMIC_3V3 | TMDSCSK388 | PROC023 | PRDN_REV.A | FY170076000102
DEVICE_TYPE_BOTTOM: C | F | E | WL_DBG | GND | 32KHz | 232_TX | 232_RX | BT_DBG | VBAT_IN | VIO_IN | 26MHz | 100 | 64 | 62 | 2 | 99 | 63 | 61 | 1 | 94V-0 | PCB-D02 | This EVB is for evaluation only; not FCC approved for resale. | WL1837MODCOM8I
PAGE_OUTLINE: 27 | 21 | 19 | 17 | 15 | 7 | 2 | 10 | A | B | C | D | E | F | G | H | J | K | L | M | N | P | R | T | 1 | 3 | 48 | 25 | 8 | 9 | 24 | 5 | 4 | 6 | 88 | 87 | 16 | 20 | 11 | 34 | 32 | 50 | 18 | 64 | 12 | 28 | 26 | 23 | 22 | 14 | 13 | AC | W | U | AG | AE | AA | AH | Y | V | AF | AD | AB
FAB_DETAIL: 10. | 11. | FINISHED BOARD THICKNESS 0.063" +/- 10% | MINIMUM TRACEWIDTH AND SPACING: 0.004/0.0036".
User.6: 171116
User.33: SL# | 01 | 02 | 03 | 04 | 05 | 06 | 07 | 08 | STRIPLINE | MICROSTRIP | COATED COPLANAR | IMPEDANCE SPECIFICATIONS | EDGE COUPLED STRIPLINE | EDGE COUPLED MICROSTRIP | TYPE | L01 | LAYER | L03&L06 | L01&L08 | TRACEWIDTH(Mils) | 25 | 4.01 | 5.50 | 4 | 4.7 | SPACING(Mils) | 7.5 | 9 | 4.5 | 7 | - | 50 | IMPEDANCE(Ohms) | 55 | 100 | 90 | REF LAYER | L04 | L02&L07 | L02
User.34: LAYER NAME | 0.0037 | 0.0045 | 0.014 | 0.008 | LAYER STACKUP | FINISHED Cu | 1oz. | X-SECTION | DIELECTRIC THICKNESS | [INCHES] | L01 | L02 | L03 | L04 | L05 | L06 | L07 | L08 | PRIMARY SIDE | PRIMARY SIDE SILKSCREEN | PRIMARY SIDE SOLDERMASK | GROUND-PLANE-1 | INNER-SIGNAL-1 | POWER-PLANE-1 | POWER-PLANE-2 | INNER-SIGNAL-2 | GROUND-PLANE-2 | SECONDARY SIDE | SECONDARY SIDE SOLDERMASK | SECONDARY SIDE SILKSCREEN
User.36: FIGURE | SIZE | 10.0 | 32.0 | 36.0 | 38.0 | 40.0 | 42.0 | 88.0 | DRILL CHART: TOP to BOTTOM | ALL UNITS ARE IN MILS | TOLERANCE | +3.0/-3.0 | +2.0/-2.0 | PLATED | NON-PLATED | QTY | 1748 | 18 | 2 | 1 | 3
